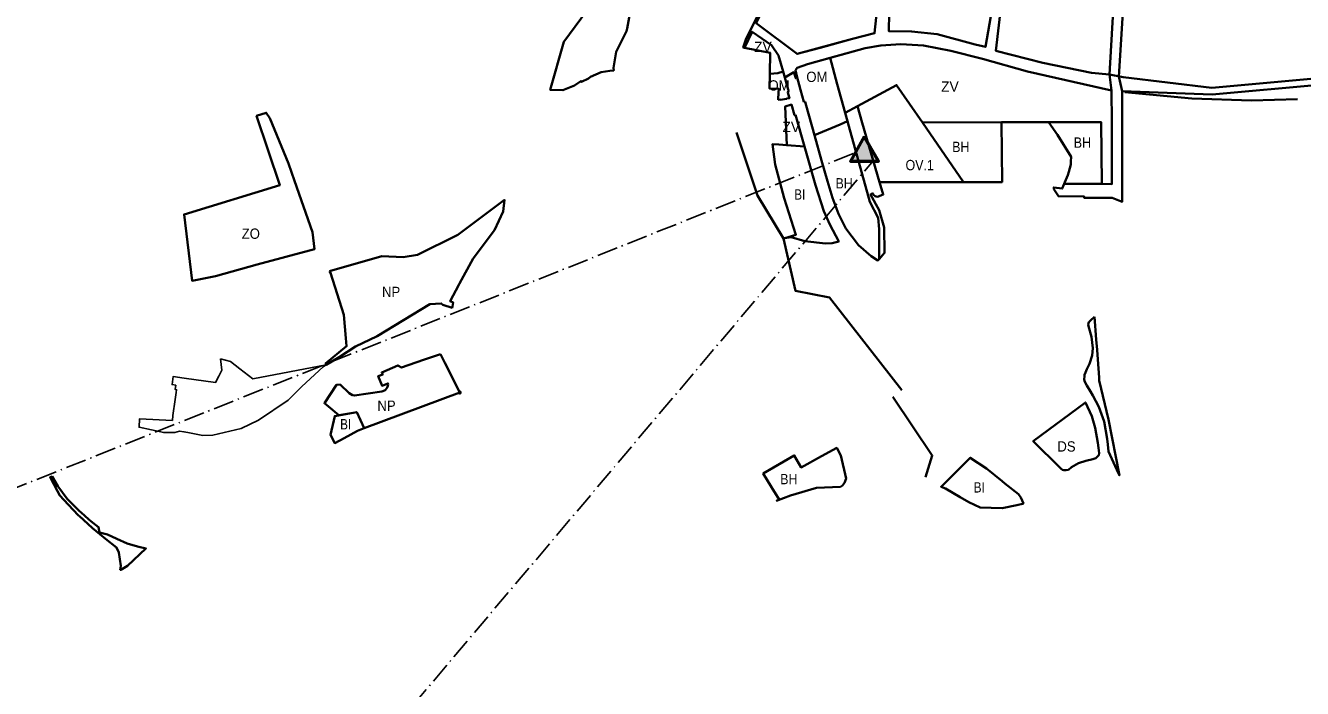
# Model space of a CAD drawing. Extents: x -650276 to -642489, y -1074311 to -1066720.
# Drawn here: x -646730 to -645245, y -1070703 to -1069933 of the extents above; entities that cross this region are included whole.
import ezdxf

# ---------------------------------------------------------------- set-up
doc = ezdxf.new("R2010")
doc.units = 0
doc.header["$LTSCALE"] = 4.8
doc.header["$PDMODE"] = 32
doc.header["$PDSIZE"] = 2.4
doc.linetypes.add('DOT_DASHED', pattern=[7.7, 5, -1.2, 0.3, -1.2])
for name, color, linetype, lineweight in [('1', 7, 'Continuous', 35), ('11', 7, 'Continuous', 35), ('12', 7, 'Continuous', 35), ('15', 7, 'Continuous', 35), ('2', 7, 'Continuous', 35), ('24', 7, 'Continuous', 35), ('40', 7, 'Continuous', 35), ('42', 7, 'Continuous', 35), ('48', 7, 'Continuous', 35), ('54', 7, 'Continuous', 35), ('55', 7, 'Continuous', 53), ('61', 7, 'Continuous', 25)]:
    doc.layers.add(name, color=color, linetype=linetype, lineweight=lineweight)
doc.layers.add('62', color=7, linetype='Continuous')

msp = doc.modelspace()

# ---------------------------------------------------------------- hatches: boundary and pattern name
at = {"layer": '55'}
msp.add_hatch(color=256, dxfattribs=at).paths.add_polyline_path([(-645754.857, -1070061.969), (-645770.808, -1070090.615), (-645738.424, -1070090.615)])

# ---------------------------------------------------------------- linework, layer by layer
at = {"layer": '1'}
for points in [[(-645772.853, -1070049.868), (-645774.423, -1070044.167), (-645783.063, -1070047.855), (-645812.76, -1070060.53)], [(-645737.756, -1070204.389), (-645737.624, -1070169.544), (-645738.79, -1070156.281), (-645748.62, -1070137.889), (-645772.853, -1070049.868)], [(-645812.76, -1070060.53), (-645804.52, -1070089.63), (-645797.66, -1070113.88), (-645791.72, -1070133.09), (-645784.83, -1070151.9), (-645784.83, -1070151.9)], [(-645784.83, -1070151.9), (-645776.26, -1070168.94), (-645761.78, -1070188.29), (-645746.73, -1070201.04), (-645739.12, -1070205.9), (-645737.756, -1070204.389)]]:
    msp.add_lwpolyline(points, dxfattribs=at)
for points in [[(-645639.638, -1070114.895), (-645594.733, -1070114.868), (-645595.2, -1070045.403), (-645687.31, -1070045.724)], [(-645522.587, -1070116.952), (-645478.664, -1070117.114), (-645479.429, -1070045.409), (-645540.433, -1070045.752), (-645530.3, -1070060.08), (-645514.49, -1070085.4), (-645514.56, -1070090.91), (-645514.61, -1070094.35), (-645517.02, -1070103.08), (-645518.35, -1070106.87), (-645521.73, -1070114.83)], [(-645862.66, -1070469.5), (-645853.98, -1070483.81), (-645856.87, -1070485.24), (-645840.59, -1070479), (-645810.44, -1070470.17), (-645782.57, -1070469.22), (-645780.38, -1070467.64), (-645777.8, -1070464.4), (-645776.04, -1070459.38), (-645782.13, -1070432.59), (-645786.9, -1070423.81), (-645804.58, -1070433.53), (-645828.24, -1070446.54), (-645836.32, -1070432.55), (-645872.35, -1070453.55)]]:
    msp.add_lwpolyline(points, close=True, dxfattribs=at)
at = {"layer": '11'}
msp.add_lwpolyline([(-645639.638, -1070114.895), (-645687.31, -1070045.724), (-645717.36, -1070002.12), (-645762.868, -1070026.606), (-645757.215, -1070045.97), (-645737.075, -1070114.955)], close=True, dxfattribs=at)
at = {"layer": '12'}
for points in [[(-645794.679, -1069970.596), (-645821, -1069978), (-645833, -1069982), (-645835, -1069985), (-645833.32, -1069991.86)], [(-645777.143, -1070034.287), (-645786.238, -1070001.251), (-645794.679, -1069970.596)], [(-645833.32, -1069991.86), (-645828.9, -1070007.76), (-645825.08, -1070021.52)], [(-645825.08, -1070021.52), (-645823.76, -1070021.67), (-645822.549, -1070025.948), (-645812.76, -1070060.53), (-645783.063, -1070047.855), (-645774.423, -1070044.167), (-645777.143, -1070034.287)]]:
    msp.add_lwpolyline(points, dxfattribs=at)
msp.add_lwpolyline([(-645855.17, -1070019.44), (-645852.36, -1070019.01), (-645852.33, -1070019.2), (-645845.37, -1070018.12), (-645845.14, -1070018.08), (-645845.17, -1070017.91), (-645841.89, -1070017.42), (-645842.238, -1070016.251), (-645843.94, -1070010.6), (-645843, -1070009), (-645842.8, -1070008.59), (-645843.22, -1070007.12), (-645849.1, -1069986.42), (-645855.54, -1069988.24), (-645864.77, -1069989.26), (-645864.97, -1070006.16), (-645854.42, -1070006.47), (-645854.65, -1070010.44)], close=True, dxfattribs=at)
at = {"layer": '15'}
for points in [[(-645738.039, -1069894.231), (-645742.967, -1069941.862), (-645768.424, -1069948.431), (-645833, -1069966), (-645880.431, -1069930.3)], [(-645876.15, -1069916.47), (-645892.09, -1069947.98), (-645895.66, -1069958.42), (-645894.25, -1069958.7), (-645885.422, -1069940.184), (-645862.782, -1069955.809), (-645854.81, -1069967.927), (-645849.1, -1069986.42), (-645847.14, -1069993.34), (-645836.64, -1069987.18), (-645834.65, -1069994.21), (-645833.32, -1069991.86), (-645835, -1069985), (-645833, -1069982), (-645821, -1069978), (-645753.706, -1069959.071), (-645735.532, -1069956.306), (-645712.222, -1069954.725), (-645686.147, -1069956.306), (-645654.145, -1069962.232), (-645617.403, -1069971.714), (-645565.133, -1069986.508), (-645467.472, -1070008.38), (-645469.701, -1069990.011), (-645490.814, -1069988.074), (-645547.4, -1069976.382), (-645601.753, -1069962.317), (-645598.491, -1069932.472)], [(-645606.07, -1069913.163), (-645614.072, -1069957.797), (-645625.979, -1069954.92), (-645670.325, -1069943.002), (-645699.889, -1069939.714), (-645726.542, -1069939.398), (-645726.131, -1069918.457)], [(-645222.809, -1069993.701), (-645350.784, -1070005.227), (-645453.852, -1069992.968), (-645469.701, -1069990.011), (-645467.472, -1070008.38), (-645467.068, -1070044.959), (-645466.96, -1070117.157), (-645478.664, -1070117.114), (-645522.587, -1070116.952), (-645524.82, -1070122.48), (-645534.63, -1070121.09), (-645534.7, -1070122.95), (-645529.17, -1070131.4), (-645499.276, -1070131.652), (-645499.142, -1070133.293), (-645466.862, -1070133.219), (-645454.881, -1070137.836), (-645455.073, -1070009.111), (-645350.591, -1070013.242), (-645221.99, -1070001.66)], [(-645757.215, -1070045.97), (-645762.868, -1070026.606), (-645777.143, -1070034.287), (-645772.853, -1070049.868), (-645748.62, -1070137.889)], [(-645737.63, -1070147.39), (-645747.67, -1070129.14), (-645745.29, -1070127.83), (-645744.73, -1070129), (-645743.87, -1070130.15), (-645742.67, -1070131.07), (-645741.83, -1070131.53), (-645740.89, -1070131.8), (-645739.41, -1070131.93), (-645738.41, -1070131.78), (-645737.48, -1070131.45), (-645734.77, -1070130.18), (-645732.91, -1070129.5), (-645737.075, -1070114.955), (-645757.215, -1070045.97)], [(-645748.62, -1070137.889), (-645738.79, -1070156.281), (-645737.624, -1070169.544), (-645737.756, -1070204.389)], [(-645737.756, -1070204.389), (-645731.3, -1070197.24), (-645731.94, -1070167.87), (-645737.63, -1070147.39)], [(-645487.361, -1070271.37), (-645491.94, -1070275.85), (-645491.94, -1070275.85), (-645493.8, -1070277.67), (-645494.57, -1070280.34), (-645494.12, -1070282.52), (-645490.79, -1070294.93), (-645489.31, -1070307.77), (-645490.03, -1070316.27), (-645493.05, -1070326.11), (-645495.44, -1070330.67), (-645496.12, -1070332.34), (-645497.83, -1070336.16), (-645498.75, -1070338.98), (-645499.01, -1070340.96), (-645499.09, -1070343.91), (-645498.74, -1070345.87), (-645498, -1070347.74), (-645496.02, -1070351.15), (-645491.97, -1070358.14), (-645488.99, -1070362.96)], [(-645487.361, -1070271.37), (-645491.94, -1070275.85), (-645491.94, -1070275.85), (-645493.8, -1070277.67), (-645494.57, -1070280.34), (-645494.12, -1070282.52), (-645490.79, -1070294.93), (-645489.31, -1070307.77), (-645490.03, -1070316.27), (-645493.05, -1070326.11), (-645495.44, -1070330.67), (-645496.12, -1070332.34), (-645497.83, -1070336.16), (-645498.75, -1070338.98), (-645499.01, -1070340.96), (-645499.09, -1070343.91), (-645498.74, -1070345.87), (-645498, -1070347.74), (-645496.02, -1070351.15), (-645491.97, -1070358.14)], [(-645458.32, -1070455.91), (-645471, -1070391), (-645481.67, -1070345.39), (-645481.65, -1070342.07), (-645483.34, -1070321.17), (-645484.27, -1070309.7), (-645485.21, -1070298.03), (-645487.361, -1070271.37)], [(-645483.34, -1070321.17), (-645484.27, -1070309.7), (-645485.21, -1070298.03), (-645487.361, -1070271.37)], [(-645482.16, -1070375.96), (-645476.12, -1070393.13), (-645472.61, -1070413.13), (-645471.87, -1070419.96), (-645470.99, -1070428.07), (-645461.32, -1070449.31), (-645458.32, -1070455.91), (-645471, -1070391), (-645481.67, -1070345.39), (-645481.65, -1070342.07), (-645483.34, -1070321.17)], [(-645491.97, -1070358.14), (-645488.99, -1070362.96), (-645482.16, -1070375.96)], [(-645488.99, -1070362.96), (-645482.16, -1070375.96), (-645476.12, -1070393.13), (-645472.61, -1070413.13), (-645471.87, -1070419.96), (-645470.99, -1070428.07), (-645461.32, -1070449.31), (-645458.32, -1070455.91)]]:
    msp.add_lwpolyline(points, dxfattribs=at)
msp.add_lwpolyline([(-646623.95, -1070529.36), (-646634.85, -1070524.43), (-646644.2, -1070522.08), (-646645.31, -1070515.85), (-646654, -1070509), (-646656.83, -1070506.66), (-646665.457, -1070499.019), (-646667.42, -1070497.28), (-646681.6, -1070482.89), (-646692.74, -1070468.28), (-646699.26, -1070457.2), (-646701.65, -1070457.93), (-646693.119, -1070474.009), (-646690.316, -1070479.212), (-646680.44, -1070489.669), (-646668.361, -1070502.459), (-646667.369, -1070503.36), (-646662.895, -1070507.428), (-646652.352, -1070517.013), (-646643.895, -1070524.284), (-646637.158, -1070529.564), (-646624.211, -1070539.711), (-646621.729, -1070545.248), (-646619.34, -1070560.95), (-646619.99, -1070565.54), (-646619.15, -1070565.53), (-646611.41, -1070560.96), (-646590.2, -1070540.66), (-646599.81, -1070538.51), (-646611.88, -1070534.82)], close=True, dxfattribs=at)
at = {"layer": '2'}
for points in [[(-645806, -1069959), (-645768.424, -1069948.431), (-645742.967, -1069941.862), (-645738.039, -1069894.231), (-645729.006, -1069844.136), (-645777.852, -1069832.241), (-645804.185, -1069825.84), (-645808.28, -1069865.39), (-645808.84, -1069870.75), (-645849.79, -1069868.4), (-645850.92, -1069863.41), (-645857.204, -1069862.954), (-645857.289, -1069863.338), (-645863.95, -1069889.468), (-645869.262, -1069905.935), (-645874.219, -1069917.496), (-645880.431, -1069930.3), (-645833, -1069966)], [(-645606.07, -1069913.163), (-645604.424, -1069900.701), (-645599.271, -1069873.685), (-645677.849, -1069855.3), (-645716.277, -1069847.01), (-645723.668, -1069891.356), (-645726.131, -1069918.457), (-645726.542, -1069939.398), (-645699.889, -1069939.714), (-645670.325, -1069943.002), (-645625.979, -1069954.92), (-645614.072, -1069957.797)], [(-645589.84, -1069875.892), (-645594.866, -1069902.242), (-645598.491, -1069932.472), (-645601.753, -1069962.317), (-645547.4, -1069976.382), (-645490.814, -1069988.074), (-645469.701, -1069990.011), (-645469.701, -1069990.011), (-645464.288, -1069895.362), (-645492.842, -1069895), (-645526.451, -1069890.745)], [(-645792.37, -1070186.01), (-645784.51, -1070183.77), (-645795.07, -1070164.26), (-645801.99, -1070148.51), (-645811.48, -1070118.65), (-645824.28, -1070073.67), (-645845.01, -1070072.12), (-645854.25, -1070071.4), (-645861.74, -1070070.95), (-645858.53, -1070094.64), (-645847.88, -1070133.4), (-645834.31, -1070176.15), (-645847.2, -1070180.14), (-645839.82, -1070178.94), (-645824.12, -1070183.63), (-645799.91, -1070186.32)], [(-646344.93, -1070382.33), (-646336.25, -1070400.875), (-646344.26, -1070403.84), (-646359.769, -1070412.361), (-646370.56, -1070418.29), (-646375.63, -1070408.76), (-646370.624, -1070386.792)], [(-645594.769, -1070494.065), (-645577.47, -1070490.3), (-645571.13, -1070488.89), (-645569.97, -1070488.3), (-645572.86, -1070481.41), (-645575.7, -1070477.77), (-645591.49, -1070465.19), (-645594.62, -1070462.7), (-645612.77, -1070447.82), (-645631.63, -1070435.3), (-645636.42, -1070439.93), (-645648.9, -1070452.38), (-645665.6, -1070469.04), (-645660.29, -1070471.12), (-645643.4, -1070481.02), (-645633.35, -1070486.91), (-645620.22, -1070493)]]:
    msp.add_lwpolyline(points, close=True, dxfattribs=at)
at = {"layer": '24'}
msp.add_lwpolyline([(-645497.81, -1070370.93), (-645497.81, -1070370.93), (-645490.19, -1070386.97), (-645486.54, -1070400.38), (-645483.29, -1070417.99), (-645482.62, -1070423.93), (-645481.93, -1070430.04), (-645482.18, -1070432.13), (-645485.67, -1070435.7), (-645489.34, -1070437.05), (-645497.33, -1070438.82), (-645505.88, -1070441.74), (-645513.81, -1070446.24), (-645517.44, -1070449.23), (-645517.95, -1070449.45), (-645520.4, -1070449.87), (-645521.41, -1070449.84), (-645522.95, -1070449.61), (-645524.42, -1070449.16), (-645525.75, -1070448.41), (-645527.34, -1070447.1), (-645558.36, -1070416.1)], close=True, dxfattribs=at)
at = {"layer": '40'}
for points in [[(-645849.1, -1069986.42), (-645854.81, -1069967.927), (-645862.782, -1069955.809), (-645885.422, -1069940.184), (-645894.25, -1069958.7), (-645864.48, -1069964.53), (-645864.77, -1069989.26), (-645855.54, -1069988.24)], [(-645595.2, -1070045.403), (-645479.429, -1070045.409), (-645478.664, -1070117.114), (-645466.96, -1070117.157), (-645467.068, -1070044.959), (-645467.472, -1070008.38), (-645565.133, -1069986.508), (-645617.403, -1069971.714), (-645654.145, -1069962.232), (-645686.147, -1069956.306), (-645712.222, -1069954.725), (-645735.532, -1069956.306), (-645753.706, -1069959.071), (-645794.679, -1069970.596), (-645786.238, -1070001.251), (-645777.143, -1070034.287), (-645762.868, -1070026.606), (-645717.36, -1070002.12), (-645687.31, -1070045.724)], [(-645834.8, -1070036.71), (-645835.91, -1070037.31), (-645839.64, -1070024.9), (-645847.08, -1070027.09), (-645845.01, -1070072.12), (-645824.28, -1070073.67), (-645824.28, -1070073.67)]]:
    msp.add_lwpolyline(points, close=True, dxfattribs=at)
at = {"layer": '42'}
for points in [[(-646417.23, -1070113.25), (-646424.17, -1070093.21), (-646446.21, -1070040.55), (-646450.22, -1070034.31), (-646461.415, -1070037.991), (-646434.503, -1070118.512), (-646545.78, -1070152.41), (-646536.47, -1070229.65), (-646509.31, -1070224.11), (-646460.8, -1070210.57)], [(-646460.8, -1070210.57), (-646393.97, -1070192.69), (-646396.51, -1070173.06), (-646417.23, -1070113.25)]]:
    msp.add_lwpolyline(points, dxfattribs=at)
at = {"layer": '48'}
msp.add_lwpolyline([(-646077.78, -1069916.11), (-646104.04, -1069951.75), (-646119.95, -1070007.73), (-646105.35, -1070008.18), (-646091.87, -1070002.66), (-646084.39, -1069997.53), (-646083.67, -1069998.4), (-646075.69, -1069994.68), (-646073.1, -1069992.61), (-646060.94, -1069987.19), (-646050.68, -1069985.78), (-646046.28, -1069985.18), (-646046.63, -1069982.04), (-646043.2, -1069963.46), (-646031.24, -1069939.45), (-646030.62, -1069936.3), (-646027.3, -1069919.47)], dxfattribs=at)
for points in [[(-646376.5, -1070218.32), (-646375.52, -1070220.21), (-646359.89, -1070269.01), (-646357.73, -1070296.13), (-646356.8, -1070305.73), (-646381.25, -1070325.85), (-646380.69, -1070327.47), (-646365.63, -1070318.37), (-646346.57, -1070305.88), (-646321.24, -1070293.85), (-646259.91, -1070256.89), (-646246.71, -1070255.96), (-646245.02, -1070257.65), (-646234.17, -1070260.88), (-646233.69, -1070259.57), (-646233.36, -1070257.04), (-646233.06, -1070254.74), (-646236.44, -1070253.13), (-646226.42, -1070234.23), (-646225.7, -1070232.93), (-646209.55, -1070203.85), (-646184.67, -1070170.61), (-646174.62, -1070149.28), (-646173.2, -1070135.64), (-646227.29, -1070176.24), (-646274.26, -1070199.6), (-646291.14, -1070202.1), (-646315.95, -1070201.09)], [(-646247.667, -1070315.004), (-646267.3, -1070321.61), (-646293.14, -1070330.3), (-646297.4, -1070328.01), (-646315.84, -1070336.13), (-646314.84, -1070338.41), (-646319.95, -1070340.42), (-646315.46, -1070351.67), (-646308.791, -1070348.855), (-646308.59, -1070350.22), (-646309.18, -1070352.77), (-646309.99, -1070354.58), (-646311.82, -1070356.89), (-646314.6, -1070358.05), (-646315.7, -1070358.27), (-646347.49, -1070363.01), (-646349.76, -1070362.69), (-646353.81, -1070360.18), (-646364.34, -1070350.19), (-646368.4, -1070350.41), (-646382.67, -1070371.94), (-646377.86, -1070375.71), (-646365.7, -1070385.89), (-646344.93, -1070382.33), (-646336.35, -1070400.9), (-646225.15, -1070359.46), (-646242.56, -1070325.1)]]:
    msp.add_lwpolyline(points, close=True, dxfattribs=at)
msp.add_point((-646225.15, -1070359.46), dxfattribs=at)
at = {"layer": '54'}
for points in [[(-645624.473, -1069340.207), (-645597.606, -1069359.137), (-645542.894, -1069403.796), (-645505.738, -1069437.197), (-645484.202, -1069466.216), (-645467.655, -1069503.794), (-645460.072, -1069535.704), (-645458, -1069561.601), (-645458, -1069658.925), (-645456, -1069668), (-645455.002, -1069859.825), (-645453.95, -1069912.05), (-645458.804, -1069992.044), (-645455.073, -1070009.111)], [(-645451.854, -1070010.265), (-645374.117, -1070017.569), (-645304.693, -1070020.185), (-645251.015, -1070018.538)], [(-645903.547, -1070057.381), (-645879.191, -1070130.665), (-645848.973, -1070180.543), (-645834.684, -1070241.324), (-645795.429, -1070249.201), (-645711.259, -1070356.569)], [(-645721.753, -1070364.565), (-645675.805, -1070432.543), (-645683.821, -1070457.746)]]:
    msp.add_lwpolyline(points, dxfattribs=at)
at = {"layer": '55', "linetype": 'DOT_DASHED', "lineweight": 25}
for p, q in [((-647060.176, -1070597.455), (-645765.418, -1070080.935)), ((-646590, -1071090), (-645744.292, -1070089.84))]:
    msp.add_line(p, q, dxfattribs=at)
at = {"layer": '55'}
msp.add_lwpolyline([(-645754.857, -1070061.969), (-645770.808, -1070090.615), (-645738.424, -1070090.615)], close=True, dxfattribs=at)
at = {"layer": '61'}
msp.add_lwpolyline([(-646503.36, -1070320.39), (-646491.81, -1070323.54), (-646481.1, -1070331.76), (-646465.85, -1070343.46), (-646380.69, -1070327.47), (-646384.18, -1070329.58), (-646408.97, -1070352.57), (-646422.07, -1070365.6), (-646424.74, -1070368.25), (-646459.18, -1070391.48), (-646479.26, -1070401.17), (-646512.38, -1070409.18), (-646523.89, -1070409.54), (-646541.25, -1070406.02), (-646545.97, -1070405.06), (-646550.91, -1070404.27), (-646556.66, -1070406.07), (-646569.39, -1070406.06), (-646598.16, -1070399.848), (-646597.44, -1070389.891), (-646559.41, -1070391.82), (-646558.74, -1070386.15), (-646556, -1070367.59), (-646554.86, -1070359.63), (-646554.86, -1070359.63), (-646554.42, -1070356.22), (-646556.1, -1070356), (-646555.42, -1070350.94), (-646559.71, -1070350.35), (-646558.49, -1070340.9), (-646545.77, -1070342.7), (-646509.08, -1070347.79), (-646505.44, -1070340.51), (-646501.94, -1070333.51)], close=True, dxfattribs=at)

# ---------------------------------------------------------------- texts
at = {"layer": '62'}
for p in [(-645883.022, -1069963.776), (-645665.601, -1070009.978), (-645850.022, -1070056.776)]:
    msp.add_text('ZV', height=12, dxfattribs=at).set_placement(p)
for s, width, p in [('OM', 0.95, (-645866.28, -1070008.561)), ('OM', 0.95, (-645822.28, -1069998.561)), ('BH', 0.9, (-645652.699, -1070079.977)), ('BH', 0.9, (-645511.328, -1070074.977)), ('OV.1', 0.9, (-645706.926, -1070101.134)), ('BH', 0.9, (-645788.337, -1070122.32)), ('BI', 0.85, (-645836.337, -1070135.32)), ('ZO', 0.95, (-646478.758, -1070180.853)), ('NP', 0.95, (-646315.631, -1070248.579)), ('NP', 0.95, (-646320.99, -1070380.819)), ('BI', 0.85, (-646364.337, -1070402.32)), ('DS', 0.95, (-645530.386, -1070428.148)), ('BH', 0.9, (-645852.646, -1070466.101)), ('BI', 0.85, (-645627.657, -1070475.713))]:
    msp.add_text(s, height=12, dxfattribs=dict(at, width=width)).set_placement(p)

doc.saveas('drawing.dxf')
